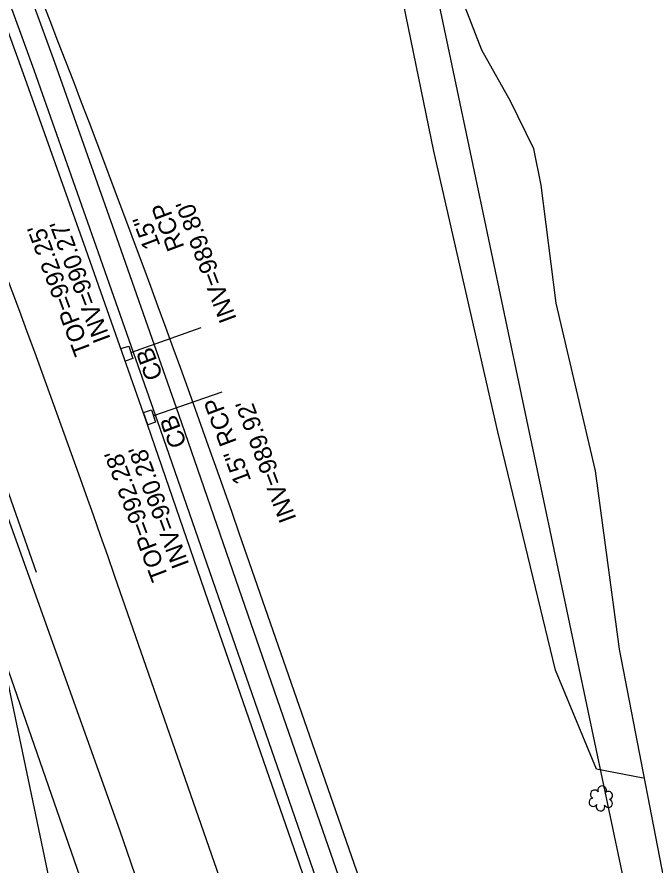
# Model space of a CAD drawing. Extents: x 1611576 to 1617186, y 899279 to 905462.
# Drawn here: x 1616215.9 to 1616361.3, y 903835.4 to 904028.8 of the extents above; entities that cross this region are included whole.
import ezdxf

# ---------------------------------------------------------------- set-up
doc = ezdxf.new("R2010")
doc.units = 0
for name, color, linetype in [('Exist Horizontal Alignment', 7, 'Continuous'), ('Exist Right of Way Line', 7, 'Continuous'), ('Exist Roads Curbs', 7, 'Continuous'), ('Exist Roads EOP', 7, 'Continuous'), ('Exist Roads EOP Other', 7, 'Continuous'), ('Exist Roads EOT', 7, 'Continuous'), ('Exist Structure Minor Catch Basin', 7, 'Continuous'), ('Exist Structure Minor Catch Basin Text', 7, 'Continuous'), ('Exist Structure Minor Catch Basin Top Elevation', 7, 'Continuous'), ('Exist Structure Minor Pipes RCP 15 Inch', 7, 'Continuous'), ('Exist Structure Minor Pipes RCP 15 Inch Invert', 7, 'Continuous'), ('Exist Structure Minor Pipes RCP 15 Inch Text', 7, 'Continuous'), ('Exist Vegetation Hedge Row', 7, 'Continuous'), ('Exist Vegetation Shrub CELL', 7, 'Continuous'), ('Exist Vegetation Woods Line', 7, 'Continuous')]:
    doc.layers.add(name, color=color, linetype=linetype)

msp = doc.modelspace()

# ---------------------------------------------------------------- linework, layer by layer
at = {"layer": 'Exist Horizontal Alignment'}
msp.add_line((1616576.74, 902927.89), (1616238.24, 903901.21), dxfattribs=at)
msp.add_arc((1612992.37, 902768.76), 3437.75, 19.23333, 21.86667, dxfattribs=at)
at = {"layer": 'Exist Right of Way Line'}
for p, q in [((1616010.65, 905462.23), (1616993.32, 900797.76)), ((1615887.44, 905426.15), (1616864.55, 900788.06)), ((1616548.32, 902918.27), (1616209.91, 903891.34))]:
    msp.add_line(p, q, dxfattribs=at)
msp.add_lwpolyline([(1616348.8, 903674.62), (1616266.57, 903911.08), (1616266.56, 903911.09)], dxfattribs=at)
msp.add_arc((1612992.37, 902768.76), 3467.75, 19.23333, 21.86667, dxfattribs=at)
at = {"layer": 'Exist Roads Curbs'}
msp.add_lwpolyline([(1616117.86, 904294.32), (1616132.6, 904254.66), (1616147.03, 904215.59), (1616161.55, 904176.09), (1616175.82, 904137.25), (1616190.47, 904097.09), (1616204.98, 904057.33), (1616219.73, 904016.73), (1616233.88, 903976.63), (1616247.93, 903936.53), (1616261.75, 903896.6), (1616275.82, 903856.12), (1616289.5, 903816.57), (1616303.58, 903775.98), (1616318, 903734.48)], dxfattribs=at)
at = {"layer": 'Exist Roads EOP'}
for points in [[(1616115.61, 904293.45), (1616130.22, 904253.88), (1616144.71, 904214.78), (1616159.36, 904175.17), (1616173.54, 904136.33), (1616188.19, 904096.22), (1616202.56, 904056.51), (1616217.36, 904015.9), (1616231.52, 903975.89), (1616245.62, 903935.7), (1616259.38, 903895.73), (1616273.35, 903855.36), (1616287.12, 903815.79), (1616301.21, 903775.08), (1616315.66, 903733.58)], [(1616115.61, 904293.45), (1616130.22, 904253.88), (1616144.71, 904214.78), (1616159.36, 904175.17), (1616173.54, 904136.33), (1616188.19, 904096.22), (1616202.56, 904056.51), (1616217.36, 904015.9), (1616231.52, 903975.89), (1616245.62, 903935.7), (1616259.38, 903895.73), (1616273.35, 903855.36), (1616287.12, 903815.79)], [(1616182.37, 904002.15), (1616180.78, 904001.18), (1616182.71, 903996.46), (1616196.01, 903962.82), (1616210.69, 903923.18), (1616225.09, 903883.2), (1616239.3, 903843.39), (1616253.05, 903803.36), (1616266.79, 903762.41), (1616281.33, 903720.95)]]:
    msp.add_lwpolyline(points, dxfattribs=at)
at = {"layer": 'Exist Roads EOP Other'}
msp.add_lwpolyline([(1616122.43, 904296.46), (1616137.34, 904256.3), (1616151.63, 904217.58), (1616166.45, 904177.4), (1616180.52, 904139.04), (1616195.16, 904098.73), (1616209.58, 904059.11), (1616224.45, 904018.46), (1616238.58, 903978.47), (1616252.68, 903938.24), (1616266.45, 903898.41), (1616280.47, 903857.78), (1616294.14, 903818.38), (1616308.3, 903777.63), (1616322.66, 903736.35)], dxfattribs=at)
at = {"layer": 'Exist Roads EOT'}
msp.add_lwpolyline([(1616220.38, 903902.1), (1616208.82, 903934.88), (1616198.96, 903962.91), (1616191.16, 903985.11), (1616188.04, 903993.96), (1616187.51, 903995.51), (1616186.9, 903997.04), (1616186.23, 903998.53), (1616185.48, 903999.99), (1616184.66, 904001.41), (1616184.11, 904002.3), (1616183.05, 904004.02), (1616181.92, 904005.69), (1616180.72, 904007.32), (1616179.46, 904008.9), (1616178.14, 904010.43), (1616178.13, 904010.44)], dxfattribs=at)
at = {"layer": 'Exist Structure Minor Catch Basin'}
for points in [[(1616242.34, 903950.91), (1616240.54, 903950.31), (1616239.57, 903953.15), (1616241.39, 903953.73), (1616242.34, 903950.91)], [(1616247.49, 903936.4), (1616245.71, 903935.79), (1616244.74, 903938.57), (1616246.55, 903939.19), (1616247.49, 903936.4)]]:
    msp.add_lwpolyline(points, dxfattribs=at)
at = {"layer": 'Exist Structure Minor Pipes RCP 15 Inch'}
for p, q in [((1616241.86, 903952.26), (1616257.87, 903957.95)), ((1616241.86, 903952.26), (1616257.87, 903957.95)), ((1616262.61, 903943.26), (1616247.04, 903937.86)), ((1616262.61, 903943.26), (1616247.04, 903937.86))]:
    msp.add_line(p, q, dxfattribs=at)
at = {"layer": 'Exist Vegetation Hedge Row'}
msp.add_lwpolyline([(1616358.61, 903855.18), (1616347.94, 903857.23), (1616338.59, 903879.82), (1616325.43, 903934.2), (1616310.92, 903998.19), (1616300.46, 904048.92), (1616299.41, 904076.85), (1616293.79, 904094.09), (1616289.23, 904099.45), (1616283.51, 904102.81), (1616273.57, 904103.44), (1616270.33, 904105.91), (1616268.99, 904109.41), (1616269.89, 904113.78), (1616274.57, 904118.52), (1616280.14, 904127.79), (1616280.93, 904138.82), (1616278.97, 904162.54), (1616274.72, 904185.17), (1616262.08, 904240.76), (1616253.29, 904278.87)], dxfattribs=at)
at = {"layer": 'Exist Vegetation Shrub CELL'}
msp.add_line((1616348.99, 903850.4), (1616348.99, 903850.4), dxfattribs=at)
for centre, radius, start, end in [((1616349.22, 903852.44), 0.99, 334.8391, 200.4717), ((1616347.51, 903851.53), 0.968, 35.8908, 245.4216), ((1616350.67, 903851.27), 0.929, 284.4567, 126.0861), ((1616347.19, 903849.7), 0.955, 95.1099, 327.9534), ((1616348.86, 903848.72), 0.984, 151.2797, 21.387), ((1616350.63, 903849.47), 0.937, 204.9913, 73.4601)]:
    msp.add_arc(centre, radius, start, end, dxfattribs=at)
at = {"layer": 'Exist Vegetation Woods Line'}
msp.add_lwpolyline([(1616365.59, 903820.6), (1616353.15, 903884.59), (1616347.73, 903925.27), (1616338.73, 903963.54), (1616335.36, 903990.43), (1616333.66, 903998.74), (1616328.38, 904009.6), (1616321.8, 904021.23), (1616318.01, 904031.04), (1616304.54, 904095.81), (1616295.76, 904137.81), (1616284.29, 904196.22), (1616273.61, 904253.55), (1616273.63, 904261.89), (1616276.22, 904274.47), (1616277.23, 904281.08), (1616276.85, 904288.34)], dxfattribs=at)

# ---------------------------------------------------------------- texts
at = {"layer": 'Exist Structure Minor Catch Basin Text'}
for p in [(1616249.23, 903946.85), (1616254.66, 903931.41)]:
    msp.add_text('CB', height=4, rotation=110.55, dxfattribs=at).set_placement(p)
at = {"layer": 'Exist Structure Minor Catch Basin Top Elevation'}
for s, p in [("TOP=992.25'", (1616232.93, 903952.43)), ("TOP=992.28'", (1616250.5, 903901))]:
    msp.add_text(s, height=4, rotation=110.55, dxfattribs=at).set_placement(p)
at = {"layer": 'Exist Structure Minor Pipes RCP 15 Inch Invert'}
for s, p in [("INV=989.80'", (1616266.02, 903959.95)), ("INV=990.27'", (1616237.3, 903955.4)), ("INV=989.92'", (1616279.63, 903914.38)), ("INV=990.28'", (1616255.22, 903903.97))]:
    msp.add_text(s, height=4, rotation=110.55, dxfattribs=at).set_placement(p)
at = {"layer": 'Exist Structure Minor Pipes RCP 15 Inch Text'}
for s, p in [('RCP', (1616254.11, 903976.32)), ('15" ', (1616248.64, 903976.66)), ('15" RCP', (1616269.33, 903923.1))]:
    msp.add_text(s, height=4, rotation=110.55, dxfattribs=at).set_placement(p)

doc.saveas('drawing.dxf')
